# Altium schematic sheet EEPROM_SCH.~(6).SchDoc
size D
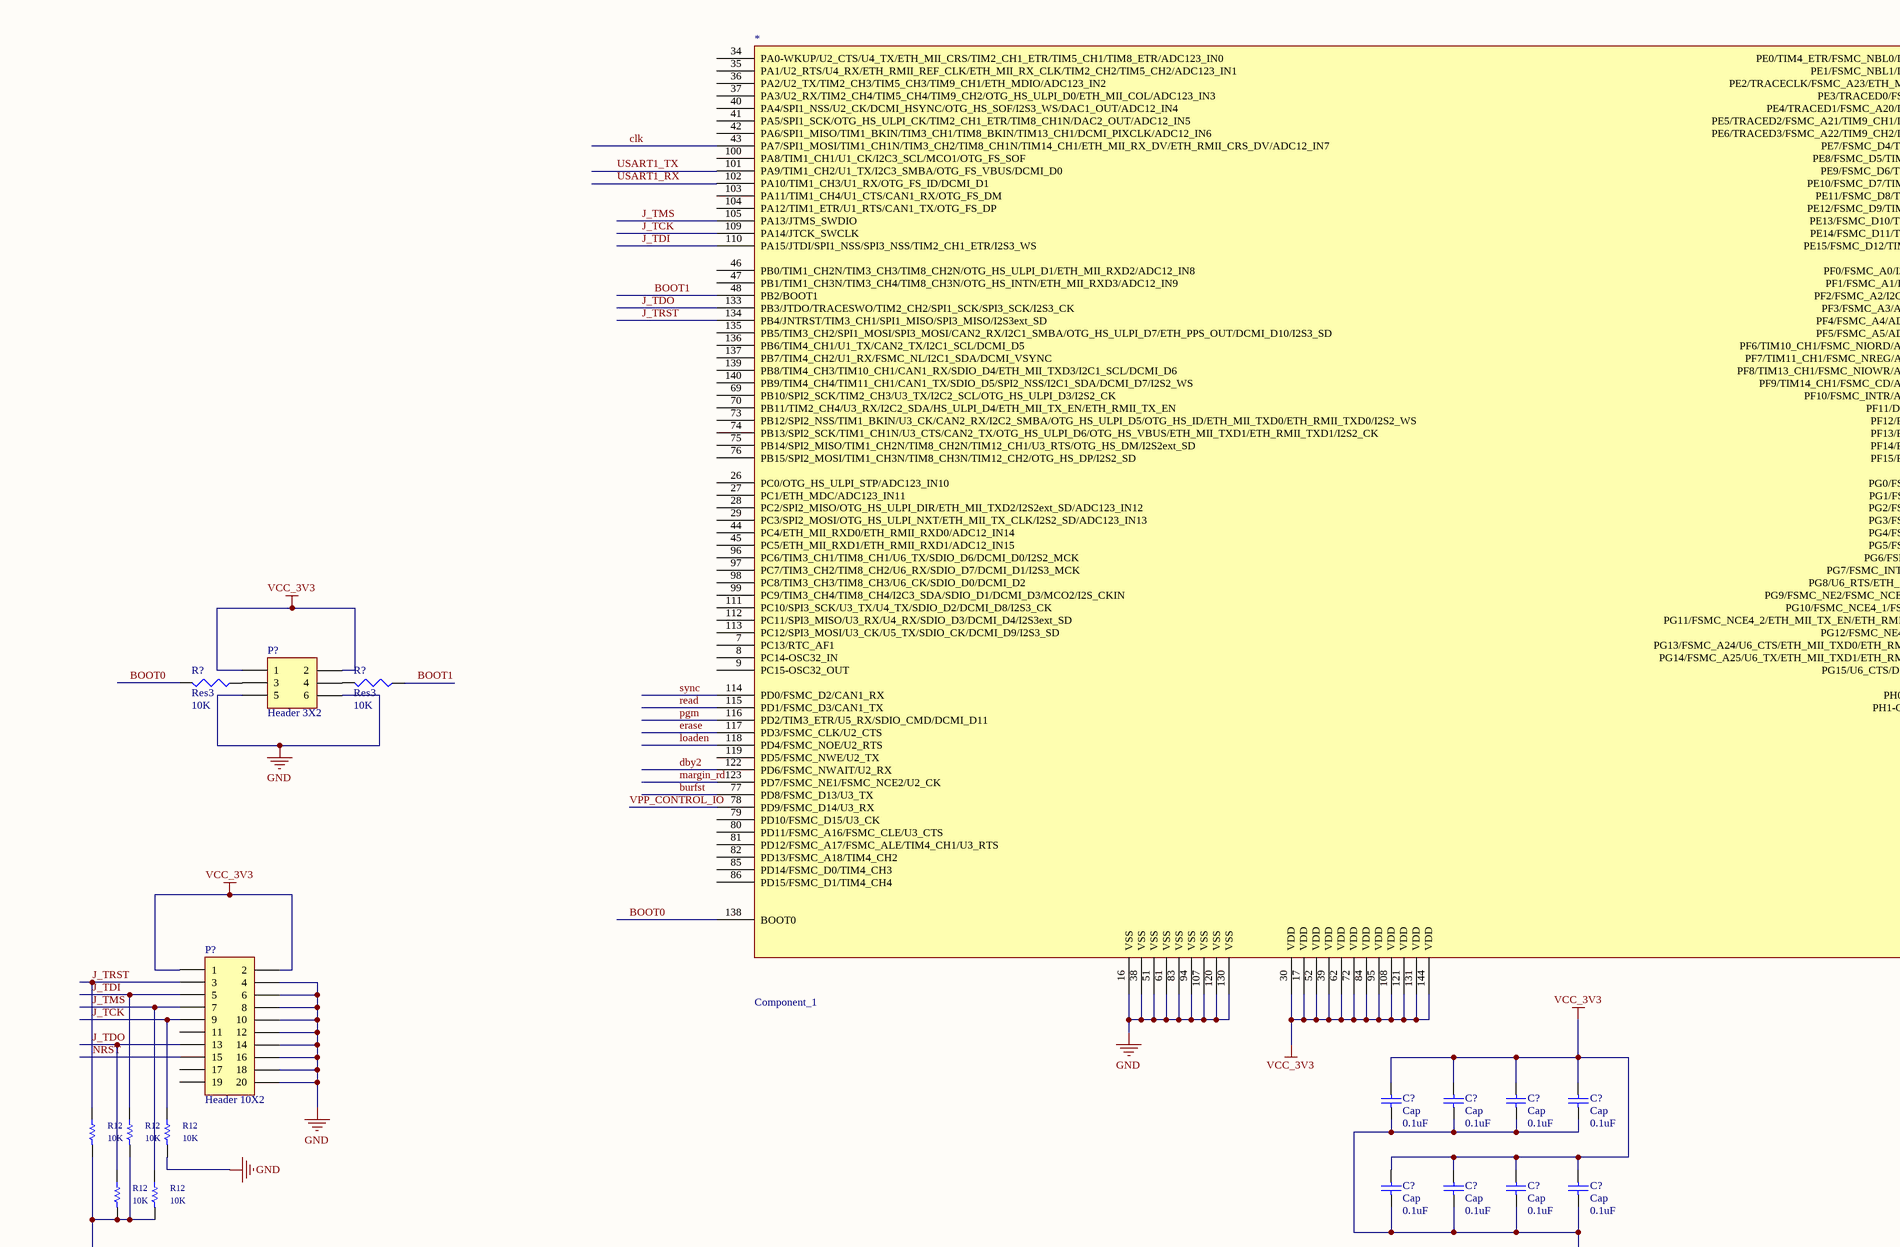
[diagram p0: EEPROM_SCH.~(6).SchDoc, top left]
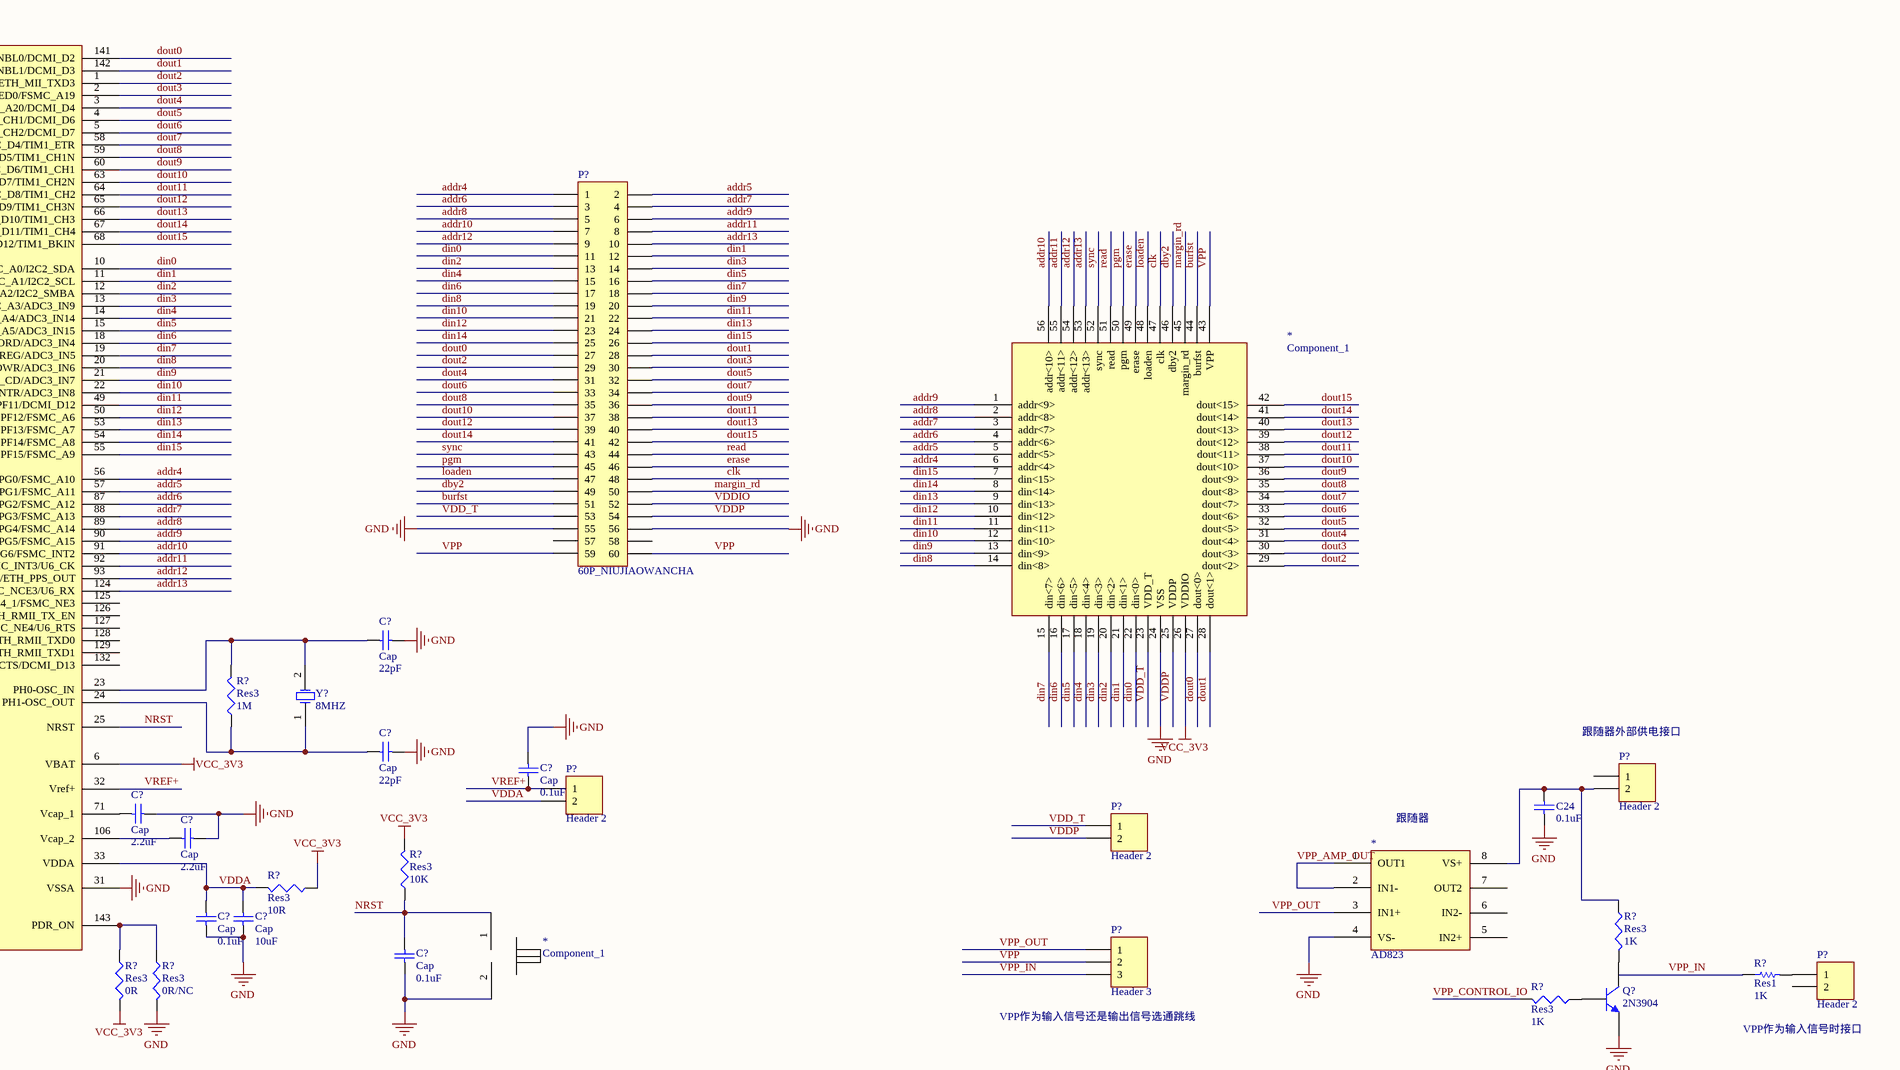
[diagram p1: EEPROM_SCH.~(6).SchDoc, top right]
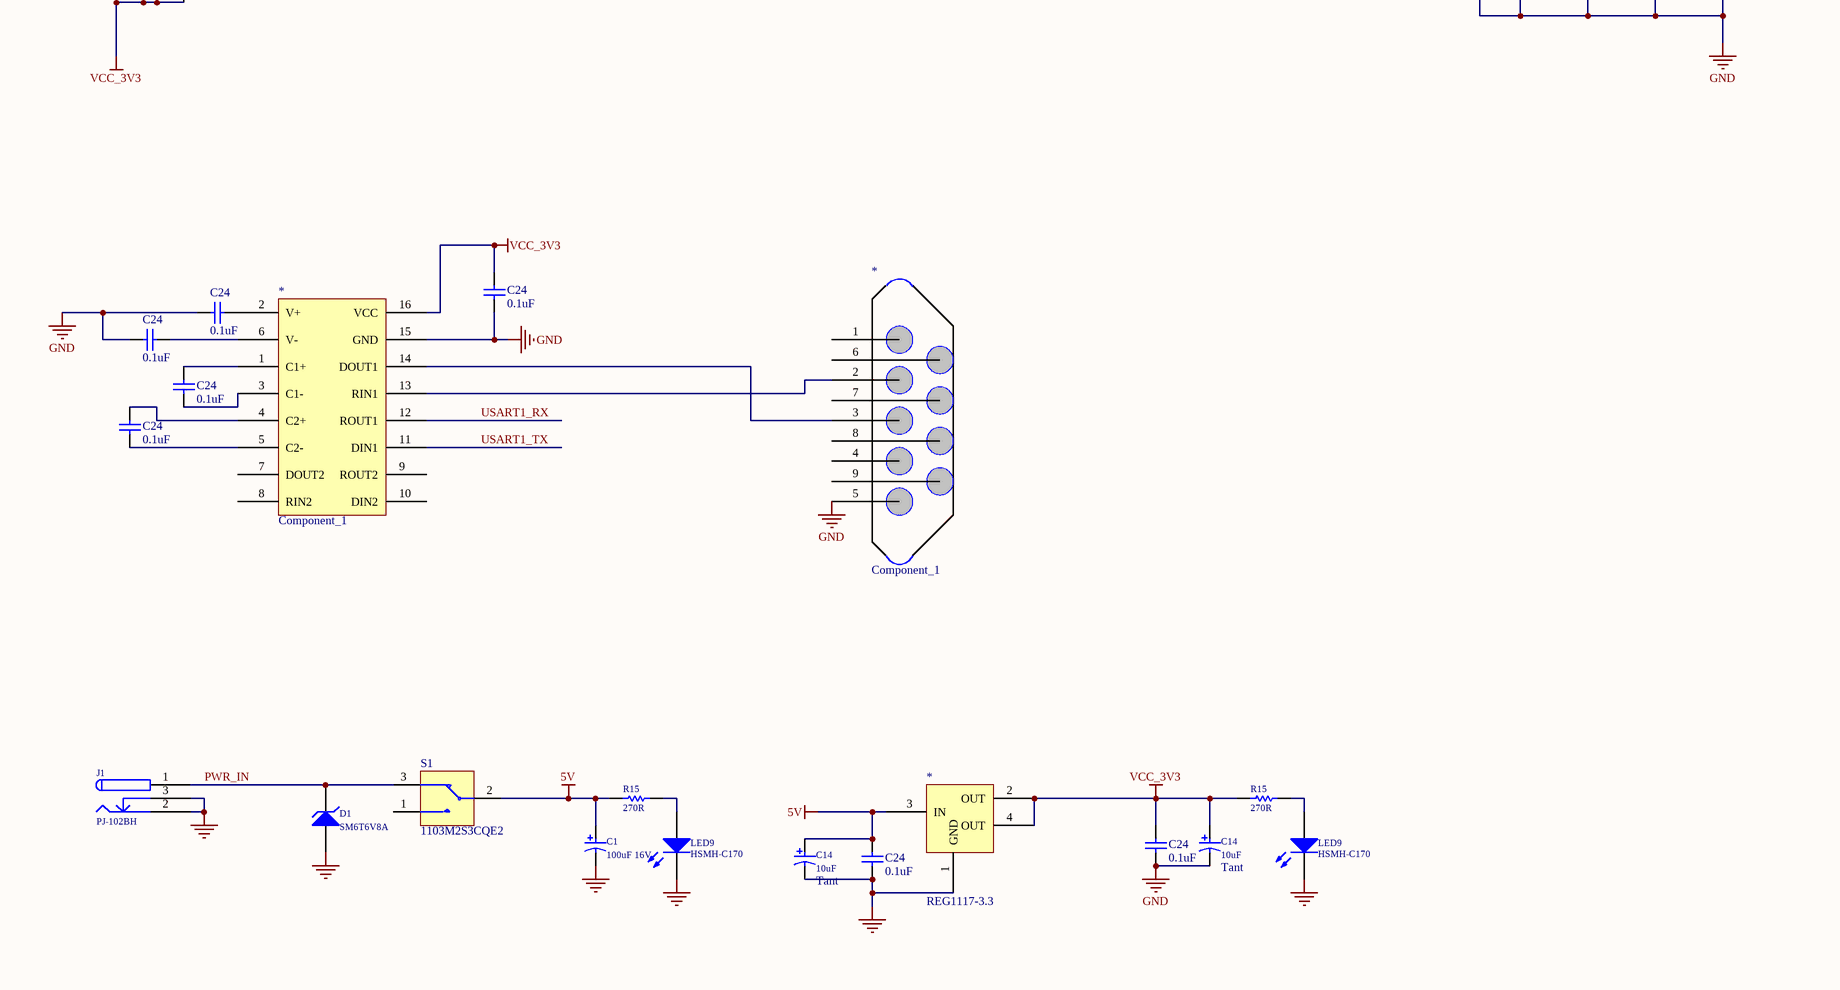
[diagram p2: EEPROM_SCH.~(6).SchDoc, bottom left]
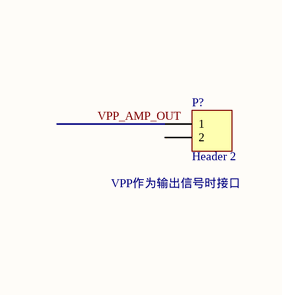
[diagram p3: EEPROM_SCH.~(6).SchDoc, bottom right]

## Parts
(Parts that share a designator on the sheet are numbered #1, #2 ... from top to bottom, then left to right.)
*#1  Component_1  [STM32F407ZGT6_LCC144]
*#2  Component_1
*#3  AD823
*#4  Component_1
*#5  Component_1
*#6  Component_1
*#7  REG1117-3.3  [PCBComponent_1]
C1  100uF 16V  [CAPPR2-5X6.8]
C14#1  10uF  Capacitor Type: Tant  [MCCT-B]
C14#2  10uF  Capacitor Type: Tant  [MCCT-B]
C24#1  0.1uF  [CC2012-0805]
C24#2  0.1uF  [CC2012-0805]
C24#3  0.1uF  [CC2012-0805]
C24#4  0.1uF  [CC2012-0805]
C24#5  0.1uF  [CC2012-0805]
C24#6  0.1uF  [CC2012-0805]
C24#7  0.1uF  [CC2012-0805]
C24#8  0.1uF  [CC2012-0805]
C?#1  Cap  value 22pF  [RAD-0.3]
C?#2  Cap  value 22pF  [RAD-0.3]
C?#3  Cap  value 0.1uF  [RAD-0.3]
C?#4  Cap  value 2.2uF  [RAD-0.3]
C?#5  Cap  value 2.2uF  [RAD-0.3]
C?#6  Cap  value 0.1uF  [RAD-0.3]
C?#7  Cap  value 10uF  [RAD-0.3]
C?#8  Cap  value 0.1uF  [RAD-0.3]
C?#9  Cap  value 0.1uF  [RAD-0.3]
C?#10  Cap  value 0.1uF  [RAD-0.3]
C?#11  Cap  value 0.1uF  [RAD-0.3]
C?#12  Cap  value 0.1uF  [RAD-0.3]
C?#13  Cap  value 0.1uF  [RAD-0.3]
C?#14  Cap  value 0.1uF  [RAD-0.3]
C?#15  Cap  value 0.1uF  [RAD-0.3]
C?#16  Cap  value 0.1uF  [RAD-0.3]
D1  SM6T6V8A  [PCBComponent_1]
J1  PJ-102BH  [PCBComponent_1]
LED9#1  HSMH-C170  [SMD _LED]
LED9#2  HSMH-C170  [SMD _LED]
P?#1  60P_NIUJIAOWANCHA  [PCBComponent_1]
P?#2  Header 3X2  [PCBComponent_1]
P?#3  Header 2  [HDR1X2]
P?#4  Header 2  [HDR1X2]
P?#5  Header 2  [HDR1X2]
P?#6  Header 3  [HDR1X3]
P?#7  Header 10X2  [HDR2X10]
P?#8  Header 2  [HDR1X2]
P?#9  Header 2  [HDR1X2]
Q?  2N3904  [TO-92A]
R12#1  10K  [CC2012-0805]
R12#2  10K  [CC2012-0805]
R12#3  10K  [CC2012-0805]
R12#4  10K  [CC2012-0805]
R12#5  10K  [CC2012-0805]
R15#1  270R  [CR2012-0805]
R15#2  270R  [CR2012-0805]
R?#1  Res3  value 10K  [J1-0603]
R?#2  Res3  value 10K  [J1-0603]
R?#3  Res3  value 1M  [J1-0603]
R?#4  Res3  value 10K  [J1-0603]
R?#5  Res3  value 10R  [J1-0603]
R?#6  Res3  value 1K  [J1-0603]
R?#7  Res3  value 0R  [J1-0603]
R?#8  Res3  value 0R/NC  [J1-0603]
R?#9  Res1  value 1K  [AXIAL-0.3]
R?#10  Res3  value 1K  [J1-0603]
S1  1103M2S3CQE2  [PCBComponent_1]
Y?  8MHZ  [R38]

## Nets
5V: *#7.3(IN) C1.1 C14#2.1 C24#8.2 R15#1.2 S1.2
GND: *#1.16(VSS) *#1.31(VSSA) *#1.38(VSS) *#1.51(VSS) *#1.61(VSS) *#1.83(VSS) *#1.94(VSS) *#1.107(VSS) *#1.120(VSS) *#1.130(VSS) *#2.24(VSS) *#3.4(VS-) *#4.2 *#5.15(GND) *#6.5 *#7.1(GND) C1.2 C14#1.2 C14#2.2 C24#1.1 C24#2.1 C24#3.1 C24#4.2 C24#7.1 C24#8.1 C?#1.1 C?#2.1 C?#3.1 C?#4.2 C?#5.2 C?#6.2 C?#7.2 C?#8.2 C?#9.1 C?#10.1 C?#11.1 C?#12.1 C?#13.1 C?#14.1 C?#15.1 C?#16.1 D1.1(A) J1.2 J1.3 LED9#1.2(K) LED9#2.2(K) P?#1.55 P?#1.56 P?#2.5 P?#2.6 P?#7.4 P?#7.6 P?#7.8 P?#7.10 P?#7.12 P?#7.14 P?#7.16 P?#7.18 P?#7.20 Q?.1(E) R12#3.2 R?#8.2
VCC_3V3: *#1.6(VBAT) *#1.17(VDD) *#1.30(VDD) *#1.39(VDD) *#1.52(VDD) *#1.62(VDD) *#1.72(VDD) *#1.84(VDD) *#1.95(VDD) *#1.108(VDD) *#1.121(VDD) *#1.131(VDD) *#1.144(VDD) *#2.26(VDDIO) *#5.16(VCC) *#7.2(OUT) *#7.4(OUT) C14#1.1 C24#3.2 C24#7.2 C?#9.2 C?#10.2 C?#11.2 C?#12.2 C?#13.2 C?#14.2 C?#15.2 C?#16.2 P?#2.1 P?#2.2 P?#7.1 P?#7.2 R12#1.2 R12#2.2 R12#4.2 R12#5.2 R15#2.2 R?#4.2 R?#5.1 R?#7.2
addr4: *#1.56(PG0/FSMC_A10) *#2.6(addr<4>) P?#1.1
addr5: *#1.57(PG1/FSMC_A11) *#2.5(addr<5>) P?#1.2
addr6: *#1.87(PG2/FSMC_A12) *#2.4(addr<6>) P?#1.3
addr7: *#1.88(PG3/FSMC_A13) *#2.3(addr<7>) P?#1.4
addr8: *#1.89(PG4/FSMC_A14) *#2.2(addr<8>) P?#1.5
addr9: *#1.90(PG5/FSMC_A15) *#2.1(addr<9>) P?#1.6
addr10: *#1.91(PG6/FSMC_INT2) *#2.56(addr<10>) P?#1.7
addr11: *#1.92(PG7/FSMC_INT3/U6_CK) *#2.55(addr<11>) P?#1.8
addr12: *#1.93(PG8/U6_RTS/ETH_PPS_OUT) *#2.54(addr<12>) P?#1.9
addr13: *#1.124(PG9/FSMC_NE2/FSMC_NCE3/U6_RX) *#2.53(addr<13>) P?#1.10
BOOT0: *#1.138(BOOT0) R?#1.2
BOOT1: *#1.48(PB2/BOOT1) R?#2.1
burfst: *#1.77(PD8/FSMC_D13/U3_TX) *#2.44(burfst) P?#1.51
clk: *#1.43(PA7/SPI1_MOSI/TIM1_CH1N/TIM3_CH2/TIM8_CH1N/TIM14_CH1/ETH_MII_RX_DV/ETH_RMII_CRS_DV/ADC12_IN7) *#2.47(clk) P?#1.48
dby2: *#1.122(PD6/FSMC_NWAIT/U2_RX) *#2.46(dby2) P?#1.49
din0: *#1.10(PF0/FSMC_A0/I2C2_SDA) *#2.22(din<0>) P?#1.11
din1: *#1.11(PF1/FSMC_A1/I2C2_SCL) *#2.21(din<1>) P?#1.12
din2: *#1.12(PF2/FSMC_A2/I2C2_SMBA) *#2.20(din<2>) P?#1.13
din3: *#1.13(PF3/FSMC_A3/ADC3_IN9) *#2.19(din<3>) P?#1.14
din4: *#1.14(PF4/FSMC_A4/ADC3_IN14) *#2.18(din<4>) P?#1.15
din5: *#1.15(PF5/FSMC_A5/ADC3_IN15) *#2.17(din<5>) P?#1.16
din6: *#1.18(PF6/TIM10_CH1/FSMC_NIORD/ADC3_IN4) *#2.16(din<6>) P?#1.17
din7: *#1.19(PF7/TIM11_CH1/FSMC_NREG/ADC3_IN5) *#2.15(din<7>) P?#1.18
din8: *#1.20(PF8/TIM13_CH1/FSMC_NIOWR/ADC3_IN6) *#2.14(din<8>) P?#1.19
din9: *#1.21(PF9/TIM14_CH1/FSMC_CD/ADC3_IN7) *#2.13(din<9>) P?#1.20
din10: *#1.22(PF10/FSMC_INTR/ADC3_IN8) *#2.12(din<10>) P?#1.21
din11: *#1.49(PF11/DCMI_D12) *#2.11(din<11>) P?#1.22
din12: *#1.50(PF12/FSMC_A6) *#2.10(din<12>) P?#1.23
din13: *#1.53(PF13/FSMC_A7) *#2.9(din<13>) P?#1.24
din14: *#1.54(PF14/FSMC_A8) *#2.8(din<14>) P?#1.25
din15: *#1.55(PF15/FSMC_A9) *#2.7(din<15>) P?#1.26
dout0: *#1.141(PE0/TIM4_ETR/FSMC_NBL0/DCMI_D2) *#2.27(dout<0>) P?#1.27
dout1: *#1.142(PE1/FSMC_NBL1/DCMI_D3) *#2.28(dout<1>) P?#1.28
dout2: *#1.1(PE2/TRACECLK/FSMC_A23/ETH_MII_TXD3) *#2.29(dout<2>) P?#1.29
dout3: *#1.2(PE3/TRACED0/FSMC_A19) *#2.30(dout<3>) P?#1.30
dout4: *#1.3(PE4/TRACED1/FSMC_A20/DCMI_D4) *#2.31(dout<4>) P?#1.31
dout5: *#1.4(PE5/TRACED2/FSMC_A21/TIM9_CH1/DCMI_D6) *#2.32(dout<5>) P?#1.32
dout6: *#1.5(PE6/TRACED3/FSMC_A22/TIM9_CH2/DCMI_D7) *#2.33(dout<6>) P?#1.33
dout7: *#1.58(PE7/FSMC_D4/TIM1_ETR) *#2.34(dout<7>) P?#1.34
dout8: *#1.59(PE8/FSMC_D5/TIM1_CH1N) *#2.35(dout<8>) P?#1.35
dout9: *#1.60(PE9/FSMC_D6/TIM1_CH1) *#2.36(dout<9>) P?#1.36
dout10: *#1.63(PE10/FSMC_D7/TIM1_CH2N) *#2.37(dout<10>) P?#1.37
dout11: *#1.64(PE11/FSMC_D8/TIM1_CH2) *#2.38(dout<11>) P?#1.38
dout12: *#1.65(PE12/FSMC_D9/TIM1_CH3N) *#2.39(dout<12>) P?#1.39
dout13: *#1.66(PE13/FSMC_D10/TIM1_CH3) *#2.40(dout<13>) P?#1.40
dout14: *#1.67(PE14/FSMC_D11/TIM1_CH4) *#2.41(dout<14>) P?#1.41
dout15: *#1.68(PE15/FSMC_D12/TIM1_BKIN) *#2.42(dout<15>) P?#1.42
erase: *#1.117(PD3/FSMC_CLK/U2_CTS) *#2.49(erase) P?#1.46
J_TCK: *#1.25(NRST) *#1.105(PA13/JTMS_SWDIO) *#1.109(PA14/JTCK_SWCLK) *#1.110(PA15/JTDI/SPI1_NSS/SPI3_NSS/TIM2_CH1_ETR/I2S3_WS) *#1.133(PB3/JTDO/TRACESWO/TIM2_CH2/SPI1_SCK/SPI3_SCK/I2S3_CK) *#1.134(PB4/JNTRST/TIM3_CH1/SPI1_MISO/SPI3_MISO/I2S3ext_SD) *#4.1 C?#8.1 P?#7.3 P?#7.5 P?#7.7 P?#7.9 P?#7.13 P?#7.15 R12#1.1 R12#2.1 R12#3.1 R12#4.1 R12#5.1 R?#4.1  [also labelled J_TDI, J_TDO, J_TMS, J_TRST, NRST]
loaden: *#1.118(PD4/FSMC_NOE/U2_RTS) *#2.48(loaden) P?#1.47
margin_rd: *#1.123(PD7/FSMC_NE1/FSMC_NCE2/U2_CK) *#2.45(margin_rd) P?#1.50
pgm: *#1.116(PD2/TIM3_ETR/U5_RX/SDIO_CMD/DCMI_D11) *#2.50(pgm) P?#1.45
PWR_IN: D1.2(K) J1.1 S1.3
read: *#1.115(PD1/FSMC_D3/CAN1_TX) *#2.51(read) P?#1.44
sync: *#1.114(PD0/FSMC_D2/CAN1_RX) *#2.52(sync) P?#1.43
USART1_RX: *#1.102(PA10/TIM1_CH3/U1_RX/OTG_FS_ID/DCMI_D1) *#5.12(ROUT1)
USART1_TX: *#1.101(PA9/TIM1_CH2/U1_TX/I2C3_SMBA/OTG_FS_VBUS/DCMI_D0) *#5.11(DIN1)
VDD_T: *#2.23(VDD_T) P?#1.53 P?#5.1
VDDA: *#1.33(VDDA) C?#6.1 C?#7.1 P?#4.2 R?#5.2
VDDIO: P?#1.52
VDDP: *#2.25(VDDP) P?#1.54 P?#5.2
VPP: *#2.43(VPP) P?#1.59 P?#1.60 P?#6.2
VPP_AMP_OUT: *#3.1(OUT1) *#3.2(IN1-) P?#9.1
VPP_CONTROL_IO: *#1.78(PD9/FSMC_D14/U3_RX) R?#10.2
VPP_IN: P?#6.3 R?#9.1
VPP_OUT: *#3.3(IN1+) P?#6.1
VREF+: *#1.32(Vref+) C?#3.2 P?#4.1
Net*#1_23: *#1.23(PH0-OSC_IN) C?#1.2 R?#3.2 Y?.2(OSC2)
Net*#1_24: *#1.24(PH1-OSC_OUT) C?#2.2 R?#3.1 Y?.1(OSC1)
Net*#1_71: *#1.71(Vcap_1) C?#4.1
Net*#1_106: *#1.106(Vcap_2) C?#5.1
Net*#1_143: *#1.143(PDR_ON) R?#7.1 R?#8.1
Net*#3_8: *#3.8(VS+) C24#1.2 P?#3.2 R?#6.1
Net*#5_1: *#5.1(C1+) C24#5.2
Net*#5_2: *#5.2(V+) C24#2.2
Net*#5_3: *#5.3(C1-) C24#5.1
Net*#5_4: *#5.4(C2+) C24#6.2
Net*#5_5: *#5.5(C2-) C24#6.1
Net*#5_6: *#5.6(V-) C24#4.1
Net*#5_13: *#5.13(RIN1) *#6.2
Net*#5_14: *#5.14(DOUT1) *#6.3
NetLED9#1_1: LED9#1.1(A) R15#1.1
NetLED9#2_1: LED9#2.1(A) R15#2.1
NetP?#2_3: P?#2.3 R?#1.1
NetP?#2_4: P?#2.4 R?#2.2
NetP?#8_1: P?#8.1 R?#9.2
NetQ?_2: Q?.2(B) R?#10.1
NetQ?_3: Q?.3(C) R?#6.2

Not connected (* = marked no-connect by the designer): *#1 7(PC13/RTC_AF1) 8(PC14-OSC32_IN) 9(PC15-OSC32_OUT) 26(PC0/OTG_HS_ULPI_STP/ADC123_IN10) 27(PC1/ETH_MDC/ADC123_IN11) 28(PC2/SPI2_MISO/OTG_HS_ULPI_DIR/ETH_MII_TXD2/I2S2ext_SD/ADC123_IN12) 29(PC3/SPI2_MOSI/OTG_HS_ULPI_NXT/ETH_MII_TX_CLK/I2S2_SD/ADC123_IN13) 34(PA0-WKUP/U2_CTS/U4_TX/ETH_MII_CRS/TIM2_CH1_ETR/TIM5_CH1/TIM8_ETR/ADC123_IN0) 35(PA1/U2_RTS/U4_RX/ETH_RMII_REF_CLK/ETH_MII_RX_CLK/TIM2_CH2/TIM5_CH2/ADC123_IN1) 36(PA2/U2_TX/TIM2_CH3/TIM5_CH3/TIM9_CH1/ETH_MDIO/ADC123_IN2) 37(PA3/U2_RX/TIM2_CH4/TIM5_CH4/TIM9_CH2/OTG_HS_ULPI_D0/ETH_MII_COL/ADC123_IN3) 40(PA4/SPI1_NSS/U2_CK/DCMI_HSYNC/OTG_HS_SOF/I2S3_WS/DAC1_OUT/ADC12_IN4) 41(PA5/SPI1_SCK/OTG_HS_ULPI_CK/TIM2_CH1_ETR/TIM8_CH1N/DAC2_OUT/ADC12_IN5) 42(PA6/SPI1_MISO/TIM1_BKIN/TIM3_CH1/TIM8_BKIN/TIM13_CH1/DCMI_PIXCLK/ADC12_IN6) 44(PC4/ETH_MII_RXD0/ETH_RMII_RXD0/ADC12_IN14) 45(PC5/ETH_MII_RXD1/ETH_RMII_RXD1/ADC12_IN15) 46(PB0/TIM1_CH2N/TIM3_CH3/TIM8_CH2N/OTG_HS_ULPI_D1/ETH_MII_RXD2/ADC12_IN8) 47(PB1/TIM1_CH3N/TIM3_CH4/TIM8_CH3N/OTG_HS_INTN/ETH_MII_RXD3/ADC12_IN9) 69(PB10/SPI2_SCK/TIM2_CH3/U3_TX/I2C2_SCL/OTG_HS_ULPI_D3/I2S2_CK) 70(PB11/TIM2_CH4/U3_RX/I2C2_SDA/HS_ULPI_D4/ETH_MII_TX_EN/ETH_RMII_TX_EN) 73(PB12/SPI2_NSS/TIM1_BKIN/U3_CK/CAN2_RX/I2C2_SMBA/OTG_HS_ULPI_D5/OTG_HS_ID/ETH_MII_TXD0/ETH_RMII_TXD0/I2S2_WS) 74(PB13/SPI2_SCK/TIM1_CH1N/U3_CTS/CAN2_TX/OTG_HS_ULPI_D6/OTG_HS_VBUS/ETH_MII_TXD1/ETH_RMII_TXD1/I2S2_CK) 75(PB14/SPI2_MISO/TIM1_CH2N/TIM8_CH2N/TIM12_CH1/U3_RTS/OTG_HS_DM/I2S2ext_SD) 76(PB15/SPI2_MOSI/TIM1_CH3N/TIM8_CH3N/TIM12_CH2/OTG_HS_DP/I2S2_SD) 79(PD10/FSMC_D15/U3_CK) 80(PD11/FSMC_A16/FSMC_CLE/U3_CTS) 81(PD12/FSMC_A17/FSMC_ALE/TIM4_CH1/U3_RTS) 82(PD13/FSMC_A18/TIM4_CH2) 85(PD14/FSMC_D0/TIM4_CH3) 86(PD15/FSMC_D1/TIM4_CH4) 96(PC6/TIM3_CH1/TIM8_CH1/U6_TX/SDIO_D6/DCMI_D0/I2S2_MCK) 97(PC7/TIM3_CH2/TIM8_CH2/U6_RX/SDIO_D7/DCMI_D1/I2S3_MCK) 98(PC8/TIM3_CH3/TIM8_CH3/U6_CK/SDIO_D0/DCMI_D2) 99(PC9/TIM3_CH4/TIM8_CH4/I2C3_SDA/SDIO_D1/DCMI_D3/MCO2/I2S_CKIN) 100(PA8/TIM1_CH1/U1_CK/I2C3_SCL/MCO1/OTG_FS_SOF) 103(PA11/TIM1_CH4/U1_CTS/CAN1_RX/OTG_FS_DM) 104(PA12/TIM1_ETR/U1_RTS/CAN1_TX/OTG_FS_DP) 111(PC10/SPI3_SCK/U3_TX/U4_TX/SDIO_D2/DCMI_D8/I2S3_CK) 112(PC11/SPI3_MISO/U3_RX/U4_RX/SDIO_D3/DCMI_D4/I2S3ext_SD) 113(PC12/SPI3_MOSI/U3_CK/U5_TX/SDIO_CK/DCMI_D9/I2S3_SD) 119(PD5/FSMC_NWE/U2_TX) 125(PG10/FSMC_NCE4_1/FSMC_NE3) 126(PG11/FSMC_NCE4_2/ETH_MII_TX_EN/ETH_RMII_TX_EN) 127(PG12/FSMC_NE4/U6_RTS) 128(PG13/FSMC_A24/U6_CTS/ETH_MII_TXD0/ETH_RMII_TXD0) 129(PG14/FSMC_A25/U6_TX/ETH_MII_TXD1/ETH_RMII_TXD1) 132(PG15/U6_CTS/DCMI_D13) 135(PB5/TIM3_CH2/SPI1_MOSI/SPI3_MOSI/CAN2_RX/I2C1_SMBA/OTG_HS_ULPI_D7/ETH_PPS_OUT/DCMI_D10/I2S3_SD) 136(PB6/TIM4_CH1/U1_TX/CAN2_TX/I2C1_SCL/DCMI_D5) 137(PB7/TIM4_CH2/U1_RX/FSMC_NL/I2C1_SDA/DCMI_VSYNC) 139(PB8/TIM4_CH3/TIM10_CH1/CAN1_RX/SDIO_D4/ETH_MII_TXD3/I2C1_SCL/DCMI_D6) 140(PB9/TIM4_CH4/TIM11_CH1/CAN1_TX/SDIO_D5/SPI2_NSS/I2C1_SDA/DCMI_D7/I2S2_WS); *#3 5(IN2+) 6(IN2-) 7(OUT2); *#5 7(DOUT2) 8(RIN2) 9(ROUT2) 10(DIN2); *#6 1 4 6 7 8 9; P?#1 57 58; P?#3 1; P?#7 11 17 19; P?#8 2; P?#9 2; S1 1

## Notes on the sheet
- (near P?#3) 跟随器外部供电接口
- (near *#3) 跟随器
- (near P?#6) VPP作为输入信号还是输出信号选通跳线
- VPP作为输入信号时接口
- (near P?#9) VPP作为输出信号时接口

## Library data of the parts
*#3 *#7 = Component_1
C1 = CAP_POLAR_1: Polar Capacitor
C14#1 C14#2 = CAP_POLAR: Polar Capacitor; AEMS Code: 2100110
C24#1-C24#8 = CAP: Capacitor
C?#1-C?#16 = Cap: Capacitor
D1 = BZG03C13: Zener Diode, 6.2V, 5W; Manufacturer: Microsemi
J1 = KLD-0202-B: Low Voltage Power Supply Connector; Manufacturer: Kycon; AEMS Code: 3510211
LED9#1 LED9#2 = HSMX-C670: Typical RED GaAs SMD LED Agilent make; AEMS Code: 2610081
P?#1 = Header 30X2: Header, 30-Pin, Dual row
P?#2 = Header 3X2: Header, 3-Pin, Dual row
P?#3-P?#5 P?#8 P?#9 = Header 2: Header, 2-Pin
P?#6 = Header 3: Header, 3-Pin
P?#7 = Header 10X2: Header, 10-Pin, Dual row
Q? = 2N3904: NPN General Purpose Amplifier
R12#1-R12#5 = RES: Resistor; AEMS Code: 1200012JT
R15#1 R15#2 = RES: Resistor; AEMS Code: 1200430
R?#1-R?#8 R?#10 = Res3: Resistor
R?#9 = Res1: Resistor
S1 = PCB_MOUNT_SWITCH: SPDT Subminiature Toggle Switch
Y? = XTAL: Crystal Oscillator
